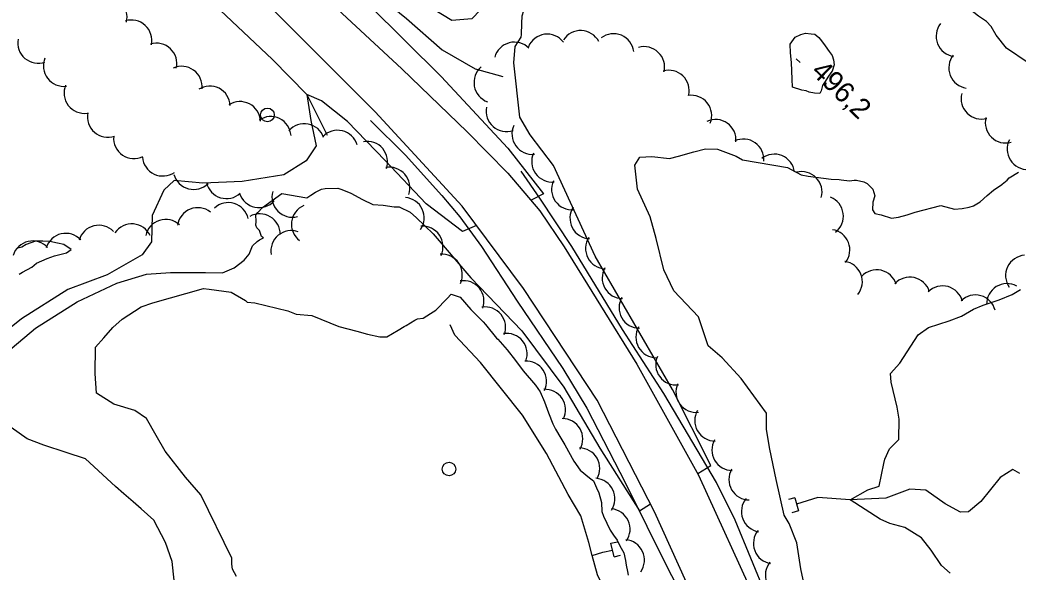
# Model space of a CAD drawing. Extents: x 642515 to 647219, y 6080136 to 6084356.
# Drawn here: x 643983 to 644129.6, y 6081021.4 to 6081102.4 of the extents above; entities that cross this region are included whole.
import ezdxf

# ---------------------------------------------------------------- set-up
doc = ezdxf.new("R2010")
doc.units = 0
for name, color, linetype in [('Level 1', 7, 'Continuous'), ('Level 2', 7, 'Continuous'), ('Level 21', 7, 'Continuous'), ('Level 26', 7, 'Continuous'), ('Level 3', 7, 'Continuous'), ('Level 36', 7, 'Continuous'), ('Level 4', 7, 'Continuous'), ('Level 44', 7, 'Continuous')]:
    doc.layers.add(name, color=color, linetype=linetype)

msp = doc.modelspace()

# ---------------------------------------------------------------- linework, layer by layer
at = {"layer": 'Level 1'}
msp.add_lwpolyline([(643982.91, 6081065.11), (643983.37, 6081065.38), (643984.76, 6081066.12), (643985.45, 6081066.72), (643987, 6081067.39), (643988.1, 6081067.78), (643989.83, 6081068.22), (643990.52, 6081068.74), (643989.47, 6081069.44), (643988.54, 6081069.65), (643987.4, 6081069.9), (643986.39, 6081069.95), (643985.31, 6081069.92), (643983.94, 6081069.47), (643983.29, 6081069.06), (643982.7, 6081068.9)], dxfattribs=at)
at = {"layer": 'Level 2'}
for points in [[(644039.57, 6081116.48), (644045.18, 6081111.72), (644048.01, 6081109.1), (644050.06, 6081107.15), (644050.68, 6081103.9), (644049.4, 6081102.61), (644046.45, 6081102.33), (644041.84, 6081105.15), (644034.41, 6081109.55), (644029.39, 6081112.59), (644025.8, 6081114.6), (644027.4, 6081111.1), (644034.25, 6081104.65), (644044.9, 6081094.12), (644054.67, 6081083.61), (644059.94, 6081076.9), (644058.09, 6081075.94)], [(644082.59, 6081035.8), (644084.51, 6081037.01), (644078.87, 6081048.14), (644067.52, 6081067.72), (644061.4, 6081081.07), (644057.97, 6081085.58), (644056.43, 6081088.13), (644055.58, 6081096.12), (644055.74, 6081098.54), (644056.62, 6081099.89), (644056.67, 6081100.29), (644056.72, 6081101.9), (644056.81, 6081103.04), (644058.26, 6081107.8), (644058.24, 6081109.32), (644057.37, 6081110.39), (644055.96, 6081111.02), (644054.73, 6081111.34), (644052.78, 6081111.69), (644052.21, 6081111.74), (644049.77, 6081113.42), (644049.1, 6081113.7)], [(644131.1, 6081096.11), (644127.93, 6081098.27), (644126.44, 6081100.18), (644125.67, 6081101.46), (644125.02, 6081102.18), (644123.84, 6081102.99), (644123.16, 6081103.51), (644121.47, 6081104.69), (644120.93, 6081104.93), (644120.48, 6081105.02), (644117.27, 6081105.49), (644115.64, 6081105.79), (644114.48, 6081106.27), (644113.36, 6081106.64), (644112.25, 6081107.09), (644110.87, 6081107.76), (644109.85, 6081108.06), (644108.78, 6081108.31), (644107.53, 6081108.43), (644106.75, 6081108.66), (644105.14, 6081108.63), (644104.57, 6081108.67)], [(644050.08, 6081072.25), (644048.02, 6081071.37), (644042.69, 6081075.43), (644036.65, 6081081.77), (644031.13, 6081087.5), (644027.32, 6081090.54), (644025.15, 6081091.46), (644025.73, 6081087.64), (644026.54, 6081083.92), (644025.08, 6081081.74), (644021.76, 6081079.67), (644015.64, 6081078.7), (644009.88, 6081078.47), (644005.68, 6081078.84), (644004.17, 6081077.45), (644002.41, 6081073.72), (644002.34, 6081069.86), (644000.94, 6081067.92), (643995.84, 6081065.01), (643990.04, 6081062.86), (643983.26, 6081058.55), (643978.38, 6081054.69)], [(644099.49, 6081013.49), (644097.73, 6081021.83), (644097.15, 6081025.66), (644096, 6081028.48), (644095.27, 6081029.72), (644094.12, 6081034.96), (644093.18, 6081039.41), (644092.67, 6081042.27), (644092.67, 6081044.69), (644088.95, 6081049.75), (644086.17, 6081052.79), (644084.12, 6081054.59), (644082.71, 6081058.84), (644079.07, 6081062.63), (644077.58, 6081065.75), (644076.47, 6081070.35), (644075.61, 6081073.51), (644073.73, 6081077.57), (644073.34, 6081081.09), (644074.06, 6081082.27), (644075.83, 6081082.39), (644078.42, 6081082.08), (644079.77, 6081082.41), (644081.99, 6081083.04), (644083.73, 6081083.48), (644085.5, 6081083.44), (644088.23, 6081082.41), (644089.15, 6081081.91), (644095.75, 6081080.74), (644097.79, 6081079.7), (644098.81, 6081079.49), (644102.19, 6081079.03), (644103.36, 6081078.99), (644103.64, 6081078.97), (644104.86, 6081078.81), (644105.54, 6081078.89), (644105.9, 6081078.88), (644107, 6081078.67), (644107.46, 6081078.42), (644108.32, 6081077.59), (644108.59, 6081076.6), (644108.29, 6081075.65), (644108.24, 6081074.56), (644108.6, 6081074.02), (644109.54, 6081073.8), (644111.06, 6081073.3), (644112.06, 6081073.49), (644113.33, 6081073.81), (644114.51, 6081074.22), (644118.31, 6081075.19)], [(644118.31, 6081075.19), (644120.32, 6081074.64), (644121.4, 6081074.76), (644122.47, 6081074.95), (644123.07, 6081075.11), (644124.07, 6081075.74), (644125.1, 6081076.65), (644126.01, 6081077.44), (644127.25, 6081078.25), (644127.29, 6081078.29), (644128.05, 6081078.91), (644128.35, 6081079.25), (644129.7, 6081080.1)], [(643977.46, 6081050.61), (643985.31, 6081057.17), (643991.41, 6081061.03), (643997.26, 6081063.76), (644001.59, 6081065.09), (644005.11, 6081065.33), (644010.26, 6081065.35), (644012.76, 6081065.27), (644014.47, 6081066.03), (644015.93, 6081067.17), (644016.67, 6081068.03), (644017.15, 6081069.27), (644017.84, 6081069.87), (644018.22, 6081070.14), (644018.77, 6081070.42), (644018.51, 6081070.64), (644018.21, 6081071.51), (644017.79, 6081071.88), (644017.68, 6081072.28), (644017.72, 6081072.84), (644017.66, 6081073.8), (644017.96, 6081074.14), (644018.63, 6081074.91), (644021.47, 6081076.95), (644025.13, 6081076.31), (644025.75, 6081076.68), (644026.44, 6081077.12), (644027.3, 6081077.58), (644027.85, 6081077.7), (644029.7, 6081077.74), (644030.28, 6081077.54), (644031.6, 6081076.99), (644033.35, 6081076.06), (644034.84, 6081075.35), (644036.38, 6081075.21), (644038, 6081075), (644038.73, 6081074.97), (644040.31, 6081074.19), (644041.25, 6081073.37), (644043.73, 6081071.04), (644049.23, 6081064.57), (644056.74, 6081056.79), (644062.92, 6081048.52), (644068.18, 6081039.54), (644074.02, 6081030.36), (644075.62, 6081031.38)], [(644014.81, 6081020.7), (644014.25, 6081021.79), (644014.12, 6081022.51), (644014.14, 6081023.4), (644009.58, 6081032.68), (644007.32, 6081035.26), (644004.32, 6081039.09), (644003.04, 6081041.42), (644001.59, 6081043.9), (643999.9, 6081045.08), (643996.78, 6081046), (643994.25, 6081047.6), (643994.06, 6081050.49), (643994.13, 6081054.36), (643995.32, 6081055.73), (643996.67, 6081057.26), (643998.04, 6081058.48), (644000.82, 6081060.28), (644002.55, 6081060.88), (644009.98, 6081062.99), (644010.8, 6081062.88), (644014.05, 6081062.45), (644016.14, 6081061.22), (644016.4, 6081061), (644017.53, 6081060.91), (644022.36, 6081059.71), (644023.6, 6081059.22), (644025.87, 6081059.05), (644029.85, 6081057.39), (644032.52, 6081056.73)], [(644119.67, 6081021.18), (644118.38, 6081022.3), (644116.86, 6081024.54), (644115.45, 6081026.38), (644113.01, 6081027.91), (644110.79, 6081028.49), (644109.38, 6081029.12), (644104.95, 6081031.96), (644107.59, 6081033.42), (644109.25, 6081033.94), (644109.92, 6081037.29), (644110.04, 6081037.94), (644110.74, 6081039.44), (644112.11, 6081040.83), (644112.15, 6081043.81), (644111.87, 6081045.57), (644110.98, 6081049.22), (644110.9, 6081050.51), (644112.25, 6081052.05), (644114.96, 6081056.18), (644116.5, 6081057.25), (644119.5, 6081058.26), (644121.31, 6081058.95), (644123.1, 6081059.95), (644124.51, 6081060.53), (644126.88, 6081061.33), (644128.76, 6081062.11), (644130.01, 6081062.83)], [(644032.52, 6081056.73), (644034.08, 6081056.27), (644035.88, 6081055.9), (644036.93, 6081055.89), (644038.59, 6081056.85), (644039.44, 6081057.39), (644039.75, 6081057.57), (644041.03, 6081058.34), (644041.42, 6081058.53), (644042.26, 6081058.62), (644043.3, 6081059.3), (644044.12, 6081059.8), (644045.77, 6081061.52), (644046.34, 6081062.16), (644047.69, 6081061.73), (644049.27, 6081059.9), (644051.08, 6081058.09), (644051.42, 6081057.71), (644053.01, 6081055.72), (644053.22, 6081055.53), (644054.57, 6081053.97), (644055.8, 6081052.44), (644056.95, 6081050.91), (644058.74, 6081048.81), (644059.45, 6081047.81), (644060.07, 6081046.36), (644060.27, 6081045.81), (644060.66, 6081044.71), (644061.29, 6081043.1), (644061.67, 6081042.32), (644062.48, 6081041.01), (644063.07, 6081040.04), (644064.36, 6081037.63), (644065.33, 6081036.32), (644066.69, 6081035.21), (644067.28, 6081034.76), (644067.72, 6081033.7), (644068.05, 6081032.96), (644068.46, 6081031.54), (644068.47, 6081030.25), (644068.72, 6081029.58), (644069.7, 6081027.51), (644070.19, 6081026.78), (644070.72, 6081026.01), (644071.14, 6081025.19), (644071.73, 6081024.15), (644071.97, 6081023.03), (644072.05, 6081022.36), (644072.24, 6081021.44), (644072.35, 6081020.89)], [(644005.8, 6081018.73), (644005.36, 6081022.88), (644004.37, 6081025.71), (644002.7, 6081028.98), (644000.83, 6081030.62), (643999.63, 6081031.67), (643998.26, 6081032.86), (643997.07, 6081033.91), (643992.62, 6081037.96), (643989.82, 6081038.89), (643986.53, 6081039.96), (643984.06, 6081040.92), (643980.52, 6081043.42)]]:
    msp.add_lwpolyline(points, dxfattribs=at)
msp.add_lwpolyline([(644096.45, 6081093.74), (644096.35, 6081096.19), (644096.22, 6081097.59), (644096.15, 6081098.87), (644096.89, 6081099.88), (644097.71, 6081100.29), (644098.42, 6081100.49), (644099.23, 6081100.38), (644099.8, 6081100.33), (644100.35, 6081099.84), (644100.74, 6081099.34), (644101.31, 6081098.61), (644101.88, 6081097.8), (644102.32, 6081097.19), (644102.52, 6081096.56), (644102.64, 6081095.84), (644102.33, 6081094.9), (644102.11, 6081094.64), (644101.77, 6081094.18), (644101.19, 6081093.26), (644100.93, 6081092.8), (644100.7, 6081092.03), (644100.52, 6081091.65), (644099.71, 6081091.69), (644098.94, 6081091.84), (644098.49, 6081092.01), (644097.88, 6081092.1), (644096.48, 6081092.58)], close=True, dxfattribs=at)
at = {"layer": 'Level 21'}
for points in [[(643940.43, 6081196.24), (643952.1, 6081182.86), (643963.75, 6081169.6), (643965.14, 6081168.01), (643970.57, 6081162.36), (643978.01, 6081154.59), (643991.25, 6081140.92), (644007.45, 6081125.12), (644020.93, 6081112.14), (644039.13, 6081095.27), (644048.72, 6081085.98), (644054.7, 6081079.93), (644059.4, 6081074.39), (644062.97, 6081069.1), (644073.62, 6081051.89), (644082.7, 6081035.6), (644091.36, 6081016.58)], [(644107.81, 6080892.05), (644105.06, 6080914.56), (644102.46, 6080933.11), (644099.42, 6080951.07), (644095.94, 6080970.61), (644095.57, 6080972.14), (644094.31, 6080977.31), (644091.19, 6080990.07), (644088.11, 6081000.67), (644082.11, 6081017.23), (644076.22, 6081030.21), (644067.81, 6081046.59), (644057, 6081062.97), (644047.97, 6081075.08), (644035.17, 6081088.96), (644020.49, 6081103.6), (644003.55, 6081120.27), (643984.06, 6081139.33), (643965.96, 6081157.92), (643948.19, 6081177.12), (643941.23, 6081185.04), (643937.99, 6081188.72)], [(644034.5, 6081087.68), (644039.65, 6081082.58), (644044.97, 6081076.65), (644047.63, 6081073.51), (644050.81, 6081069.15), (644056.04, 6081061.12), (644062.75, 6081051.26), (644066.28, 6081045.4), (644071.99, 6081034.38), (644078.25, 6081021.75), (644080.14, 6081018.15)], [(644102.17, 6080992.65), (644098.87, 6081001.1), (644092.66, 6081017.83), (644088.1, 6081028.97), (644085.32, 6081034.48), (644077.59, 6081047.56), (644071.54, 6081056.99), (644064.07, 6081069.15), (644059.39, 6081076.25), (644056.64, 6081080.24)]]:
    msp.add_lwpolyline(points, dxfattribs=at)
at = {"layer": 'Level 26'}
for p, q in [((644096.85, 6081032.27), (644095.89, 6081032.01)), ((644096.85, 6081032.27), (644097.37, 6081030.33)), ((644097.37, 6081030.33), (644096.41, 6081030.07)), ((644069.8, 6081025.58), (644070.78, 6081025.8)), ((644070.28, 6081023.6), (644069.8, 6081025.58)), ((644070.28, 6081023.6), (644071.24, 6081023.84))]:
    msp.add_line(p, q, dxfattribs=at)
at = {"layer": 'Level 3'}
msp.add_line((644097.06, 6081096.72), (644097.63, 6081096.16), dxfattribs=at)
at = {"layer": 'Level 36'}
for centre in [(644019.37, 6081088.49), (644046.04, 6081036.48)]:
    msp.add_circle(centre, 1, dxfattribs=at)
at = {"layer": 'Level 4'}
for points in [[(643974.56, 6081165.25), (643978.15, 6081161.19), (643982.77, 6081156.41), (643986.17, 6081152.82), (643992.59, 6081146.31), (643999.04, 6081139.83), (644005.41, 6081133.87), (644014.06, 6081125.7), (644020.29, 6081120.18), (644025.8, 6081114.6), (644033.86, 6081107.47), (644039.8, 6081102.65), (644045.01, 6081098.02), (644049.89, 6081095.25), (644053.95, 6081094.11)], [(643954.01, 6081161.54), (643959.06, 6081155.55), (643962.31, 6081152.39), (643964.6, 6081150.02), (643970.99, 6081143.14), (643976.72, 6081137.23), (643978.67, 6081135.39), (643984.43, 6081129.96), (643991.03, 6081122.97), (643995.54, 6081117.98), (644000.22, 6081114.48), (644004.21, 6081111.21), (644010.73, 6081105.51), (644020.11, 6081096.62), (644025.15, 6081091.46), (644028.16, 6081085.51)], [(644086.7, 6080978.03), (644086.06, 6080979.79), (644085.36, 6080982.52), (644085.52, 6080984.95), (644085.36, 6080987.88), (644084.29, 6080990.71), (644082.32, 6080994.24), (644079.94, 6080998.51), (644078.71, 6081002.45), (644076.47, 6081005.32), (644073.72, 6081009.16), (644071.55, 6081013.93), (644069.81, 6081016.95), (644067.86, 6081020.93), (644067.08, 6081023.8), (644066.57, 6081025.67), (644065.42, 6081029.62), (644063.53, 6081032.72), (644060.35, 6081038.74), (644056.83, 6081044.39), (644050.67, 6081052.1), (644046.91, 6081056.15), (644046.9, 6081056.16), (644046.19, 6081057.68)], [(644129.9, 6081035.8), (644128.86, 6081036.41), (644127, 6081035.24), (644124.16, 6081031.73), (644122.37, 6081030.2), (644121.16, 6081030.12), (644118.94, 6081031.38), (644116.07, 6081033.36), (644113.72, 6081033.52), (644110.22, 6081032.2), (644104.95, 6081031.96), (644100.21, 6081032.32), (644097.11, 6081031.31)], [(644067.08, 6081023.8), (644068.62, 6081024.26), (644070.04, 6081024.58)]]:
    msp.add_lwpolyline(points, dxfattribs=at)
at = {"layer": 'Level 44'}
for centre, start, end in [((643995.74, 6081102.85), 346.014, 105.9919), ((643999.39, 6081099.42), 347.3713, 107.3492), ((644120.6, 6081100.04), 141.7802, 261.7581), ((644065.38, 6081097.88), 27.6354, 147.6133), ((644070.2, 6081097.41), 7.0822, 127.0602), ((643985.7, 6081099.06), 169.1299, 289.1078), ((644003.06, 6081096.02), 346.6579, 106.6359), ((644055.65, 6081096.17), 44.6287, 164.6067), ((644060.47, 6081097.35), 37.5022, 157.4802), ((644074.71, 6081095.51), 346.1815, 106.1594), ((643989.45, 6081095.68), 157.4303, 277.4082), ((644122.46, 6081095.4), 141.7802, 261.7581), ((644006.77, 6081092.62), 354.3449, 114.3229), ((644052.71, 6081093.23), 130.1208, 250.0987), ((644078.32, 6081092.04), 346.1815, 106.1594), ((643992.49, 6081091.71), 157.4303, 277.4082), ((644010.9, 6081089.72), 2.8351, 122.813), ((644124.26, 6081090.87), 165.4403, 285.4183), ((644015.34, 6081087.44), 2.8351, 122.813), ((644081.63, 6081088.37), 338.5559, 98.5338), ((643995.92, 6081088.19), 168.827, 288.8049), ((644054.49, 6081089.04), 168.8435, 288.8214), ((644019.84, 6081085.24), 4.0024, 123.9803), ((644085.2, 6081084.81), 354.93, 114.9079), ((644127.82, 6081087.36), 165.4403, 285.4183), ((644024.79, 6081084.19), 19.3209, 139.2989), ((644029.68, 6081083.23), 16.7382, 136.7161), ((644058.29, 6081085.69), 155.5189, 275.4968), ((643999.77, 6081085.07), 175.5993, 295.5773), ((644034.03, 6081081.58), 340.8843, 100.8622), ((644089.29, 6081081.94), 354.93, 114.9079), ((644131.03, 6081083.47), 152.6685, 272.6464), ((644061.19, 6081081.62), 155.5189, 275.4968), ((644004, 6081082.51), 184.5035, 304.4814), ((644093.82, 6081079.72), 7.9305, 127.9084), ((644037.3, 6081077.8), 340.8843, 100.8622), ((644097.84, 6081077.15), 344.4791, 104.4571), ((644008.52, 6081080.54), 195.1476, 315.1255), ((644013.35, 6081079.19), 192.6011, 312.579), ((644064.1, 6081077.55), 155.5189, 275.4968), ((644018.14, 6081077.87), 197.9075, 317.8854), ((644023.03, 6081076.46), 164.5866, 284.5646), ((644013.62, 6081072.61), 13.0601, 133.0381), ((644039.4, 6081073.36), 325.2814, 85.2593), ((644100.97, 6081073.61), 308.0601, 68.038), ((644009.13, 6081071.86), 51.8569, 171.8348), ((644025.89, 6081072.41), 112.8658, 232.8437), ((644066.81, 6081073.31), 147.3099, 267.2878), ((644004.42, 6081070.13), 47.7434, 167.7214), ((644018.24, 6081070.96), 359.2231, 119.201), ((643989.74, 6081068.09), 42.9733, 162.9513), ((643994.6, 6081069.28), 44.2766, 164.2545), ((643999.44, 6081069.48), 25.3631, 145.341), ((644022.87, 6081068.5), 69.8674, 189.8454), ((644042.16, 6081069.14), 334.6668, 94.6448), ((644101.93, 6081068.66), 321.4378, 81.4157), ((643984.87, 6081066.97), 42.9733, 162.9513), ((644069.1, 6081068.87), 147.3099, 267.2878), ((644045, 6081065.03), 334.6668, 94.6448), ((644103.76, 6081064), 321.4378, 81.4157), ((644130.8, 6081064.88), 94.4446, 214.4225), ((644071.54, 6081064.52), 149.6928, 269.6708), ((644108.86, 6081062.74), 17.5734, 137.5513), ((644048.18, 6081061.14), 339.5222, 99.5002), ((644113.74, 6081061.66), 17.5734, 137.5513), ((644118.55, 6081060.37), 14.5792, 134.5571), ((644128.01, 6081060.71), 61.6138, 181.5918), ((644074.02, 6081060.17), 149.6928, 269.6708), ((644123.37, 6081059.04), 14.5792, 134.5571), ((644051.36, 6081057.28), 339.2204, 99.1983), ((644076.49, 6081055.83), 149.6928, 269.6708), ((644054.52, 6081053.4), 339.2204, 99.1983), ((644057.39, 6081049.35), 333.7114, 93.6894), ((644079.41, 6081051.82), 156.3071, 276.285), ((644060.17, 6081045.19), 333.7114, 93.6894), ((644082.37, 6081047.79), 156.3071, 276.285), ((644085.14, 6081043.59), 150.0571, 270.035), ((644062.69, 6081040.9), 330.0848, 90.0628), ((644087.65, 6081039.27), 150.0571, 270.035), ((644065.19, 6081036.57), 330.0848, 90.0628), ((644090.15, 6081034.94), 150.0571, 270.035), ((644067.43, 6081032.12), 326.2508, 86.2288), ((644092, 6081030.24), 140.607, 260.585), ((644069.64, 6081027.64), 324.9796, 84.9575), ((644093.76, 6081025.56), 140.607, 260.585), ((644071.75, 6081023.11), 324.9796, 84.9575), ((644095.51, 6081020.88), 140.607, 260.585)]:
    msp.add_arc(centre, 3, start, end, dxfattribs=at)

# ---------------------------------------------------------------- texts
at = {"layer": 'Level 3'}
msp.add_text('496,2', height=3, rotation=315.59, dxfattribs=at).set_placement((644099.09, 6081094.68))

doc.saveas('drawing.dxf')
